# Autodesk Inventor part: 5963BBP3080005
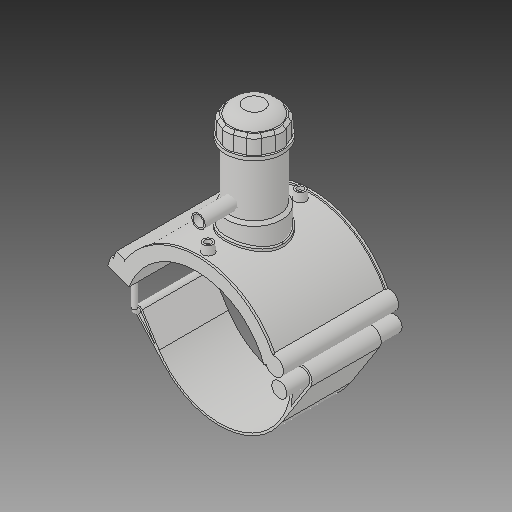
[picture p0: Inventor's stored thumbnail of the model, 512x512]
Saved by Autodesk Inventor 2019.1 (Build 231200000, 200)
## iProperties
Created: 2017-07
Part Number: 5963BBP3080005
Material: Generic
Description: PLASSON TAPPING SADDLE 8''IPS x 1/2''IPS
Document SubType Name: Modeling
Designer: KIM
Density: 1 g/cm^3
Appearance: Default
Author: KIM
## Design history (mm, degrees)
derived "5963BBP_5963BUP.ipt"
feature "Solid1::5963BBP_5963BUP.ipt"
feature "Solid2::5963BBP_5963BUP.ipt"
feature "Solid3::5963BBP_5963BUP.ipt"
tag "TaggingFeature1"
body "Solid1"
body "Solid2"
body "Solid3"
other parameters: "d_" = 218.7, "B_" = 179.832, "L_" = 176.022, "d_t" = 6, "H_2" = 177.038, "H_1" = 65.024, "d_1" = 21.2, "H_" = 85.09, "d1" = 253.692, "d148" = 3.2805, "d160" = 3.2805, "d169" = 3.2805, "d192" = 6.9984, "d0" = 218.7, "d2" = 269.748, "d3" = 54.675, "d4" = 176.022, "d5" = 0, "d6" = 0.1, "d8" = 0, "d19" = 6, "d20" = 6, "d21" = 105.6132, "d23" = 0, "d24" = 52.8066, "d26" = 0, "d27" = 3, "d28" = 3, "d29" = 3, "d30" = 72.9, "d31" = 6, "d32" = 0, "d33" = 0, "d34" = 0.6, "d40" = 131.91984, "d41" = 87.48, "d43" = 0, "d45" = 0, "d47" = 232.4592, "d70" = 15, "d72" = 0, "d73" = 6, "d75" = 5, "d76" = 0, "d77" = 10.935, "d78" = 139.35, "d79" = 15, "d80" = 70.4088, "d82" = 5 deg, "d84" = 4, "d85" = 14, "d86" = 0, "d87" = 3, "d88" = 0, "d89" = 1, "d90" = 1, "d91" = 140.8176, "d92" = 0, "d93" = 0.5, "d94" = 115.10526, "d96" = 258.76584, "d97" = 3.52044, "d98" = 0, "d102" = 2.187, "d120" = 140 deg, "d121" = 24.228, "d122" = 20 deg, "d123" = 507.384, "d124" = 152.2152, "d126" = 0, "d143" = 225.261, "d145" = 26.91692, "d149" = 3.2805, "d150" = 29.60862, "d153" = 176.022, "d154" = 0, "d156" = 126.846, "d157" = 160 deg, "d159" = 6.9984, "d161" = 3.2805, "d162" = 105.6132, "d163" = 0, "d164" = 109.35, "d167" = 21.87, "d168" = 123.7522, "d170" = 3.2805, "d172" = 0, "d173" = 1, "d175" = 109.35, "d176" = 20 deg, "d177" = 15.309, "d178" = 34.992, "d180" = 0, "d183" = 13.9968, "d184" = 12.2472, "d185" = 57.20715, "d186" = 57.20715, "d187" = 126.846, "d188" = 10.4976, "d189" = 15.309, "d190" = 0, "d191" = 190.269, "d193" = 6.9984, "d194" = 6.16077, "d195" = 90 deg, "d197" = 0, "d199" = 0, "d200" = 17.496, "d202" = 0, "d203" = 177.038, "d204" = 83.106, "d205" = 61.236, "d206" = 74.358, "d207" = 132.7785, "d208" = 138.08964, "d209" = 164.64534, "d210" = 75.2328, "d211" = 87.48, "d212" = 69.984, "d213" = 48.9816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
